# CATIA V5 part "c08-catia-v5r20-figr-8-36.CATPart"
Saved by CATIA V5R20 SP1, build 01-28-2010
Part number: Part1
Bounding box of the stored display mesh (mm): x -75 to 75, y -75 to 75, z 0 to 20
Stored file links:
  D:\v5_r20\psrt_files_downloaded\c08-catia-v5r20-prt\c08-catia-v5r20-figr-8-36.CATPart
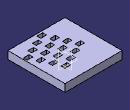
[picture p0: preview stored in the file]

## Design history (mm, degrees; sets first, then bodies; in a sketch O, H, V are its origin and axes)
Body1 (main body)
  Sketch1 on xy-plane, origin (0, 0, 0), H (1, 0, 0), V (0, 1, 0)
    line L1 (-75, 75) -> (75, 75)
    line L2 (75, 75) -> (75, -75)
    line L3 (75, -75) -> (-75, -75)
    line L4 (-75, -75) -> (-75, 75)
    axis line L5 (75, -75) -> (-75, 75)
    length L3 = 150
    length L2 = 150
    horizontal: L1 H, L3 H
    vertical: L2 V, L4 V
    midpoint: O L5
  Pad1: profile Sketch1, direction (0, 0, 1), length 20
  Sketch2 on face of Pad1, origin (0, 0, 20), H (1, 0, 0), V (0, 1, 0)
    line L1 (25, 40) -> (40, 40)
    line L2 (40, 40) -> (40, 30)
    line L3 (40, 30) -> (25, 30)
    line L4 (25, 30) -> (25, 40)
    reference projected line E1 (75, -75) -> (75, 75) from edge [face of Pad1 | face of Pad1]
    reference projected line E2 (75, 75) -> (-75, 75) from edge [face of Pad1 | face of Pad1]
    length L3 = 15
    length L4 = 10
    distance L2 E1 = 35
    distance L1 E2 = 35
    horizontal: L1 H, L3 H
    vertical: L2 V, L4 V
  Pocket1: profile Sketch2, direction (0, 0, -1), through (limit type 3)
  RectPattern1: of Pocket1, direction 1 instances 4, spacing 25, along edge [face of Pad1 | face of Pad1] reversed, direction 2 instances 4, spacing 25, along edge [face of Pad1 | face of Pad1], rotation -25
